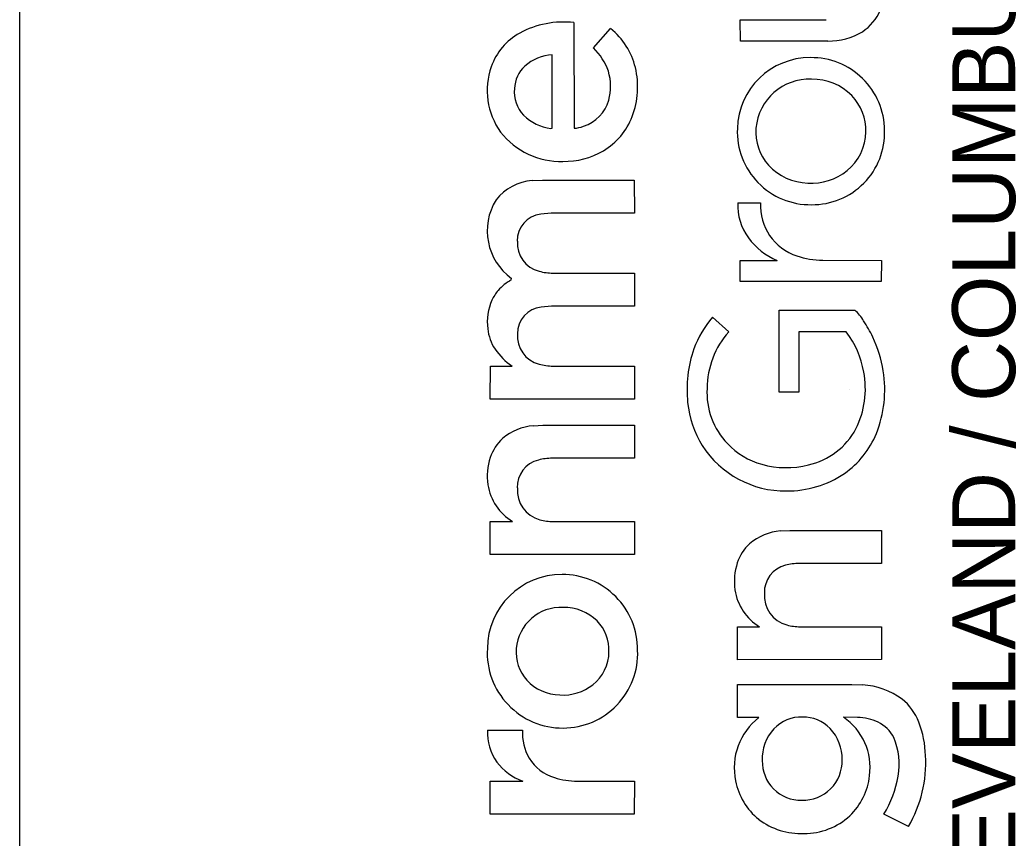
# Model space of a CAD drawing. Extents: x 0 to 34, y 0 to 22.
# Drawn here: x 32 to 32.901, y 3.094 to 3.835 of the extents above; entities that cross this region are included whole.
import ezdxf

# ---------------------------------------------------------------- set-up
doc = ezdxf.new("R2010")
doc.units = 0
doc.layers.add('SH_Border', color=7, linetype='Continuous')
doc.layers.add('SH_Data', color=7, linetype='Continuous')

msp = doc.modelspace()

# ---------------------------------------------------------------- linework, layer by layer
at = {"layer": 'SH_Border'}
msp.add_line((32, 0.5), (32, 21.5), dxfattribs=at)
at = {"layer": 'SH_Data'}
for p, q in [((32.50108, 3.83209), (32.50118, 3.73657)), ((32.65154, 3.83443), (32.72905, 3.8345)), ((32.65165, 3.81543), (32.65154, 3.83443)), ((32.51882, 3.80927), (32.53422, 3.82662)), ((32.73073, 3.81543), (32.65165, 3.81543)), ((32.48144, 3.73644), (32.48144, 3.80296)), ((32.48016, 3.73628), (32.48144, 3.73644)), ((32.46329, 3.68915), (32.47259, 3.68968)), ((32.47259, 3.68968), (32.55557, 3.68968)), ((32.55557, 3.68968), (32.55571, 3.65982)), ((32.64932, 3.66907), (32.66978, 3.66907)), ((32.48058, 3.65981), (32.47102, 3.65881)), ((32.55571, 3.65982), (32.48058, 3.65981)), ((32.65152, 3.61699), (32.68476, 3.617)), ((32.65152, 3.598), (32.65152, 3.61699)), ((32.72605, 3.61703), (32.7791, 3.61696)), ((32.7791, 3.61696), (32.77903, 3.598)), ((32.48218, 3.60553), (32.55571, 3.60548)), ((32.55571, 3.60548), (32.55571, 3.57568)), ((32.44443, 3.59922), (32.44455, 3.60072)), ((32.77903, 3.598), (32.65152, 3.598)), ((32.4809, 3.57567), (32.47143, 3.57474)), ((32.55571, 3.57568), (32.4809, 3.57567)), ((32.6868, 3.57185), (32.75516, 3.57192)), ((32.6868, 3.49778), (32.6868, 3.57185)), ((32.62636, 3.56548), (32.64114, 3.55241)), ((32.70448, 3.55241), (32.70432, 3.49775)), ((32.74737, 3.55227), (32.70448, 3.55241)), ((32.42542, 3.49152), (32.42545, 3.52138)), ((32.42545, 3.52138), (32.44515, 3.52138)), ((32.48206, 3.52138), (32.55571, 3.52136)), ((32.55571, 3.52136), (32.55571, 3.49156)), ((32.70432, 3.49775), (32.6868, 3.49778)), ((32.75, 3.5), (32.75, 3.5)), ((32.55571, 3.49156), (32.42542, 3.49152)), ((32.46439, 3.46736), (32.47289, 3.46783)), ((32.47289, 3.46783), (32.55571, 3.46783)), ((32.55571, 3.46783), (32.55571, 3.43804)), ((32.55571, 3.43804), (32.4814, 3.43796)), ((32.42542, 3.38066), (32.44552, 3.38071)), ((32.42542, 3.35086), (32.42542, 3.38066)), ((32.48222, 3.38071), (32.55569, 3.38071)), ((32.55569, 3.38071), (32.55571, 3.35096)), ((32.68784, 3.3722), (32.69634, 3.37266)), ((32.69634, 3.37266), (32.77916, 3.37266)), ((32.77916, 3.37266), (32.77917, 3.34287)), ((32.55571, 3.35096), (32.42542, 3.35086)), ((32.77917, 3.34287), (32.70485, 3.3428)), ((32.64888, 3.2855), (32.66897, 3.28555)), ((32.64888, 3.25569), (32.64888, 3.2855)), ((32.70568, 3.28555), (32.77915, 3.28555)), ((32.77915, 3.28555), (32.77917, 3.25579)), ((32.77917, 3.25579), (32.64888, 3.25569)), ((32.6489, 3.20336), (32.64889, 3.23322)), ((32.64889, 3.23322), (32.75236, 3.23322)), ((32.75236, 3.23322), (32.76191, 3.23285)), ((32.66836, 3.20336), (32.6489, 3.20336)), ((32.75763, 3.20356), (32.74487, 3.20361)), ((32.42299, 3.19193), (32.45454, 3.19193)), ((32.42542, 3.14577), (32.45473, 3.14579)), ((32.42542, 3.11593), (32.42542, 3.14577)), ((32.50413, 3.14581), (32.55571, 3.14573)), ((32.55571, 3.14573), (32.55565, 3.11593)), ((32.55565, 3.11593), (32.42542, 3.11593)), ((32.8036, 3.10491), (32.7812, 3.11598))]:
    msp.add_line(p, q, dxfattribs=at)
for points in [[(32.50108, 3.83209), (32.50118, 3.73657)], [(32.73073, 3.81543), (32.65165, 3.81543), (32.65154, 3.83443), (32.72905, 3.8345)], [(32.51882, 3.80927), (32.53422, 3.82662)], [(32.48016, 3.73628), (32.48144, 3.73644), (32.48144, 3.80296)], [(32.46329, 3.68915), (32.47259, 3.68968), (32.55557, 3.68968), (32.55571, 3.65982), (32.48058, 3.65981), (32.47102, 3.65881)], [(32.64932, 3.66907), (32.66978, 3.66907)], [(32.72605, 3.61703), (32.7791, 3.61696), (32.77903, 3.598), (32.65152, 3.598)], [(32.65152, 3.598), (32.65152, 3.61699), (32.68476, 3.617)], [(32.48218, 3.60553), (32.55571, 3.60548), (32.55571, 3.57568), (32.4809, 3.57567), (32.47143, 3.57474)], [(32.44443, 3.59922), (32.44455, 3.60072)], [(32.74737, 3.55227), (32.70448, 3.55241), (32.70432, 3.49775), (32.6868, 3.49778), (32.6868, 3.57185), (32.75516, 3.57192)], [(32.62636, 3.56548), (32.64114, 3.55241)], [(32.42542, 3.49152), (32.42545, 3.52138), (32.44515, 3.52138)], [(32.48206, 3.52138), (32.55571, 3.52136), (32.55571, 3.49156), (32.42542, 3.49152)], [(32.46439, 3.46736), (32.47289, 3.46783), (32.55571, 3.46783), (32.55571, 3.43804), (32.4814, 3.43796)], [(32.42542, 3.35086), (32.42542, 3.38066), (32.44552, 3.38071)], [(32.48222, 3.38071), (32.55569, 3.38071), (32.55571, 3.35096), (32.42542, 3.35086)], [(32.68784, 3.3722), (32.69634, 3.37266), (32.77916, 3.37266), (32.77917, 3.34287), (32.70485, 3.3428)], [(32.64888, 3.25569), (32.64888, 3.2855), (32.66897, 3.28555)], [(32.70568, 3.28555), (32.77915, 3.28555), (32.77917, 3.25579), (32.64888, 3.25569)], [(32.66836, 3.20336), (32.6489, 3.20336), (32.64889, 3.23322), (32.75236, 3.23322), (32.76191, 3.23285)], [(32.75763, 3.20356), (32.74487, 3.20361)], [(32.42299, 3.19193), (32.45454, 3.19193)], [(32.50413, 3.14581), (32.55571, 3.14573), (32.55565, 3.11593), (32.42542, 3.11593)], [(32.42542, 3.11593), (32.42542, 3.14577), (32.45473, 3.14579)], [(32.8036, 3.10491), (32.7812, 3.11598)]]:
    msp.add_lwpolyline(points, dxfattribs=at)
for centre, radius, start, end in [((32.739, 3.85901), 0.04201, 303.10391, 338.15613), ((32.739, 3.85901), 0.04201, 303.10391, 338.15613), ((32.49176, 3.74874), 0.08387, 83.62118, 118.28448), ((32.49176, 3.74874), 0.08387, 83.62118, 118.28448), ((32.47894, 3.77368), 0.05583, 118.82935, 160.62242), ((32.47894, 3.77368), 0.05583, 118.82935, 160.62242), ((32.49399, 3.7763), 0.06443, 13.53275, 51.36266), ((32.49399, 3.7763), 0.06443, 13.53275, 51.36266), ((32.7321, 3.87256), 0.05715, 268.62699, 301.47779), ((32.7321, 3.87256), 0.05715, 268.62699, 301.47779), ((32.4844, 3.76071), 0.04236, 94.01311, 130.88062), ((32.4844, 3.76071), 0.04236, 94.01311, 130.88062), ((32.48033, 3.77018), 0.05485, 19.0387, 45.44322), ((32.48033, 3.77018), 0.05485, 19.0387, 45.44322), ((32.71435, 3.73484), 0.06552, 89.48213, 178.77752), ((32.71435, 3.73484), 0.06552, 89.48213, 178.77752), ((32.71582, 3.73414), 0.06623, 0.42265, 90.7613), ((32.71582, 3.73414), 0.06623, 0.42265, 90.7613), ((32.48697, 3.77074), 0.06438, 160.52138, 215.78155), ((32.48697, 3.77074), 0.06438, 160.52138, 215.78155), ((32.47703, 3.7709), 0.02985, 132.98553, 177.1802), ((32.47703, 3.7709), 0.02985, 132.98553, 177.1802), ((32.48724, 3.77433), 0.04701, 344.60723, 17.00675), ((32.48724, 3.77433), 0.04701, 344.60723, 17.00675), ((32.48289, 3.77384), 0.0758, 339.35431, 13.37708), ((32.48289, 3.77384), 0.0758, 339.35431, 13.37708), ((32.71397, 3.73244), 0.04846, 87.68827, 175.01696), ((32.71397, 3.73244), 0.04846, 87.68827, 175.01696), ((32.71659, 3.73036), 0.05052, 44.91202, 90.75914), ((32.71659, 3.73036), 0.05052, 44.91202, 90.75914), ((32.47824, 3.76966), 0.03114, 175.00138, 223.2876), ((32.47824, 3.76966), 0.03114, 175.00138, 223.2876), ((32.71955, 3.73452), 0.04549, 358.32279, 43.83486), ((32.71955, 3.73452), 0.04549, 358.32279, 43.83486), ((32.49895, 3.77177), 0.03504, 288.01084, 343.55364), ((32.49895, 3.77177), 0.03504, 288.01084, 343.55364), ((32.48546, 3.77826), 0.04232, 225.06454, 262.79701), ((32.48546, 3.77826), 0.04232, 225.06454, 262.79701), ((32.49548, 3.76982), 0.0626, 300.94393, 338.73223), ((32.49548, 3.76982), 0.0626, 300.94393, 338.73223), ((32.48908, 3.77516), 0.06872, 217.74341, 271.65606), ((32.48908, 3.77516), 0.06872, 217.74341, 271.65606), ((32.50129, 3.75678), 0.02021, 269.70042, 294.87295), ((32.50129, 3.75678), 0.02021, 269.70042, 294.87295), ((32.71483, 3.7334), 0.06606, 177.53728, 270.94524), ((32.71483, 3.7334), 0.06606, 177.53728, 270.94524), ((32.71085, 3.73311), 0.0453, 175.51467, 221.42047), ((32.71085, 3.73311), 0.0453, 175.51467, 221.42047), ((32.71671, 3.73271), 0.06536, 269.30834, 1.67905), ((32.71671, 3.73271), 0.06536, 269.30834, 1.67905), ((32.71931, 3.73374), 0.04572, 308.90382, 359.30947), ((32.71931, 3.73374), 0.04572, 308.90382, 359.30947), ((32.49204, 3.77702), 0.07055, 269.20529, 300.33566), ((32.49204, 3.77702), 0.07055, 269.20529, 300.33566), ((32.71399, 3.73734), 0.05046, 222.66255, 268.37331), ((32.71399, 3.73734), 0.05046, 222.66255, 268.37331), ((32.71567, 3.73859), 0.05178, 266.55312, 308.67253), ((32.71567, 3.73859), 0.05178, 266.55312, 308.67253), ((32.46638, 3.64404), 0.04521, 93.91118, 142.30723), ((32.46638, 3.64404), 0.04521, 93.91118, 142.30723), ((32.47585, 3.64373), 0.05319, 148.28793, 233.9556), ((32.47585, 3.64373), 0.05319, 148.28793, 233.9556), ((32.69878, 3.66662), 0.04952, 177.16211, 216.28024), ((32.69878, 3.66662), 0.04952, 177.16211, 216.28024), ((32.71735, 3.66638), 0.04764, 176.76988, 252.15044), ((32.71735, 3.66638), 0.04764, 176.76988, 252.15044), ((32.47384, 3.63499), 0.02399, 96.75763, 181.6251), ((32.47384, 3.63499), 0.02399, 96.75763, 181.6251), ((32.47577, 3.63241), 0.02597, 175.81573, 256.16716), ((32.47577, 3.63241), 0.02597, 175.81573, 256.16716), ((32.70975, 3.67555), 0.06366, 216.91526, 246.88619), ((32.70975, 3.67555), 0.06366, 216.91526, 246.88619), ((32.7269, 3.69175), 0.07473, 251.13884, 269.34694), ((32.7269, 3.69175), 0.07473, 251.13884, 269.34694), ((32.4817, 3.65053), 0.04501, 254.34629, 270.61033), ((32.4817, 3.65053), 0.04501, 254.34629, 270.61033), ((32.4638, 3.56267), 0.04137, 117.91625, 139.24296), ((32.4638, 3.56267), 0.04137, 117.91625, 139.24296), ((32.46194, 3.56452), 0.03875, 139.52447, 154.84698), ((32.46194, 3.56452), 0.03875, 139.52447, 154.84698), ((32.47144, 3.5612), 0.04877, 156.06382, 187.3493), ((32.47144, 3.5612), 0.04877, 156.06382, 187.3493), ((32.47421, 3.55056), 0.02434, 96.5532, 179.94902), ((32.47421, 3.55056), 0.02434, 96.5532, 179.94902), ((32.72498, 3.53937), 0.04438, 30.98913, 47.16099), ((32.72498, 3.53937), 0.04438, 30.98913, 47.16099), ((32.70163, 3.50187), 0.09855, 139.79476, 159.13696), ((32.70163, 3.50187), 0.09855, 139.79476, 159.13696), ((32.67091, 3.50018), 0.11106, 25.30315, 33.96179), ((32.67091, 3.50018), 0.11106, 25.30315, 33.96179), ((32.46461, 3.55974), 0.04181, 186.5579, 213.38846), ((32.46461, 3.55974), 0.04181, 186.5579, 213.38846), ((32.47608, 3.54863), 0.02628, 175.722, 255.78627), ((32.47608, 3.54863), 0.02628, 175.722, 255.78627), ((32.69899, 3.50079), 0.07753, 138.25804, 179.70064), ((32.69899, 3.50079), 0.07753, 138.25804, 179.70064), ((32.67889, 3.50099), 0.08556, 10.07509, 36.83189), ((32.67889, 3.50099), 0.08556, 10.07509, 36.83189), ((32.6704, 3.49987), 0.11166, 8.80339, 25.33484), ((32.6704, 3.49987), 0.11166, 8.80339, 25.33484), ((32.47886, 3.57078), 0.0598, 214.70433, 235.68724), ((32.47886, 3.57078), 0.0598, 214.70433, 235.68724), ((32.7187, 3.49968), 0.11536, 161.14379, 185.62812), ((32.7187, 3.49968), 0.11536, 161.14379, 185.62812), ((32.48195, 3.56518), 0.0438, 253.66719, 270.14979), ((32.48195, 3.56518), 0.0438, 253.66719, 270.14979), ((32.68425, 3.50057), 0.08036, 333.46689, 11.03668), ((32.68425, 3.50057), 0.08036, 333.46689, 11.03668), ((32.67564, 3.49977), 0.10649, 338.28866, 9.28548), ((32.67564, 3.49977), 0.10649, 338.28866, 9.28548), ((32.68811, 3.49732), 0.06676, 176.66577, 223.6912), ((32.68811, 3.49732), 0.06676, 176.66577, 223.6912), ((32.69336, 3.49699), 0.08987, 185.50773, 212.01294), ((32.69336, 3.49699), 0.08987, 185.50773, 212.01294), ((32.46871, 3.41767), 0.04988, 94.97056, 130.22484), ((32.46871, 3.41767), 0.04988, 94.97056, 130.22484), ((32.69868, 3.49547), 0.0652, 282.88151, 331.81475), ((32.69868, 3.49547), 0.0652, 282.88151, 331.81475), ((32.69835, 3.49168), 0.08241, 305.03061, 337.67573), ((32.69835, 3.49168), 0.08241, 305.03061, 337.67573), ((32.46348, 3.42602), 0.04016, 132.22383, 161.68229), ((32.46348, 3.42602), 0.04016, 132.22383, 161.68229), ((32.69045, 3.50011), 0.07039, 224.02147, 253.88), ((32.69045, 3.50011), 0.07039, 224.02147, 253.88), ((32.69211, 3.49748), 0.08908, 212.70222, 270.71399), ((32.69211, 3.49748), 0.08908, 212.70222, 270.71399), ((32.47872, 3.42158), 0.05602, 162.27398, 187.79173), ((32.47872, 3.42158), 0.05602, 162.27398, 187.79173), ((32.47482, 3.41206), 0.02498, 103.68683, 182.21395), ((32.47482, 3.41206), 0.02498, 103.68683, 182.21395), ((32.48108, 3.39196), 0.04601, 89.60515, 105.33026), ((32.48108, 3.39196), 0.04601, 89.60515, 105.33026), ((32.69318, 3.51254), 0.08309, 254.45353, 283.9512), ((32.69318, 3.51254), 0.08309, 254.45353, 283.9512), ((32.69429, 3.49979), 0.09138, 269.3273, 304.19632), ((32.69429, 3.49979), 0.09138, 269.3273, 304.19632), ((32.47027, 3.42141), 0.04763, 188.96462, 238.69865), ((32.47027, 3.42141), 0.04763, 188.96462, 238.69865), ((32.47735, 3.40897), 0.02757, 175.58441, 255.13816), ((32.47735, 3.40897), 0.02757, 175.58441, 255.13816), ((32.48183, 3.42286), 0.04215, 254.08913, 270.52838), ((32.48183, 3.42286), 0.04215, 254.08913, 270.52838), ((32.69216, 3.32251), 0.04988, 94.97056, 130.22484), ((32.69216, 3.32251), 0.04988, 94.97056, 130.22484), ((32.68694, 3.33085), 0.04016, 132.22383, 161.68229), ((32.68694, 3.33085), 0.04016, 132.22383, 161.68229), ((32.70217, 3.32642), 0.05602, 162.27398, 187.79173), ((32.70217, 3.32642), 0.05602, 162.27398, 187.79173), ((32.70453, 3.29679), 0.04601, 89.60515, 105.33026), ((32.70453, 3.29679), 0.04601, 89.60515, 105.33026), ((32.69828, 3.31689), 0.02498, 103.68683, 182.21395), ((32.69828, 3.31689), 0.02498, 103.68683, 182.21395), ((32.49014, 3.26543), 0.0674, 89.84756, 179.64047), ((32.49014, 3.26543), 0.0674, 89.84756, 179.64047), ((32.49057, 3.26474), 0.0681, 359.54009, 90.21138), ((32.49057, 3.26474), 0.0681, 359.54009, 90.21138), ((32.69372, 3.32624), 0.04763, 188.96462, 238.69865), ((32.69372, 3.32624), 0.04763, 188.96462, 238.69865), ((32.7008, 3.31381), 0.02757, 175.58441, 255.13816), ((32.7008, 3.31381), 0.02757, 175.58441, 255.13816), ((32.48923, 3.26263), 0.0404, 87.04809, 175.57259), ((32.48923, 3.26263), 0.0404, 87.04809, 175.57259), ((32.49204, 3.25999), 0.04299, 45.84264, 90.98008), ((32.49204, 3.25999), 0.04299, 45.84264, 90.98008), ((32.49458, 3.26421), 0.03821, 357.88569, 44.15902), ((32.49458, 3.26421), 0.03821, 357.88569, 44.15902), ((32.70529, 3.32769), 0.04215, 254.08913, 270.52838), ((32.70529, 3.32769), 0.04215, 254.08913, 270.52838), ((32.49083, 3.26209), 0.06819, 176.8344, 270.40384), ((32.49083, 3.26209), 0.06819, 176.8344, 270.40384), ((32.48729, 3.2625), 0.03848, 175.15378, 221.14706), ((32.48729, 3.2625), 0.03848, 175.15378, 221.14706), ((32.49123, 3.26139), 0.06749, 270.06243, 2.37759), ((32.49123, 3.26139), 0.06749, 270.06243, 2.37759), ((32.49446, 3.26318), 0.0383, 308.28936, 359.43468), ((32.49446, 3.26318), 0.0383, 308.28936, 359.43468), ((32.48919, 3.26607), 0.04228, 223.09994, 268.80895), ((32.48919, 3.26607), 0.04228, 223.09994, 268.80895), ((32.49096, 3.2679), 0.04418, 266.56515, 308.06078), ((32.49096, 3.2679), 0.04418, 266.56515, 308.06078), ((32.75907, 3.16789), 0.06503, 53.40344, 87.49062), ((32.75907, 3.16789), 0.06503, 53.40344, 87.49062), ((32.76517, 3.18039), 0.05141, 21.60748, 50.5577), ((32.76517, 3.18039), 0.05141, 21.60748, 50.5577), ((32.70292, 3.15813), 0.05692, 127.37482, 192.22468), ((32.70292, 3.15813), 0.05692, 127.37482, 192.22468), ((32.70693, 3.16927), 0.0346, 88.47302, 136.42562), ((32.70693, 3.16927), 0.0346, 88.47302, 136.42562), ((32.70814, 3.16963), 0.03424, 44.27195, 90.47623), ((32.70814, 3.16963), 0.03424, 44.27195, 90.47623), ((32.71421, 3.15829), 0.05472, 352.1125, 55.92295), ((32.71421, 3.15829), 0.05472, 352.1125, 55.92295), ((32.75666, 3.15725), 0.04633, 65.01687, 88.8011), ((32.75666, 3.15725), 0.04633, 65.01687, 88.8011), ((32.7626, 3.17155), 0.03085, 26.26808, 63.80301), ((32.7626, 3.17155), 0.03085, 26.26808, 63.80301), ((32.73069, 3.16714), 0.08835, 1.15143, 21.3627), ((32.73069, 3.16714), 0.08835, 1.15143, 21.3627), ((32.46616, 3.18882), 0.04329, 175.87313, 216.34747), ((32.46616, 3.18882), 0.04329, 175.87313, 216.34747), ((32.50087, 3.18948), 0.04639, 176.9688, 209.60636), ((32.50087, 3.18948), 0.04639, 176.9688, 209.60636), ((32.71141, 3.16602), 0.0401, 137.46739, 182.33237), ((32.71141, 3.16602), 0.0401, 137.46739, 182.33237), ((32.70368, 3.166), 0.03996, 358.57141, 43.53765), ((32.70368, 3.166), 0.03996, 358.57141, 43.53765), ((32.73565, 3.16154), 0.05953, 349.30734, 23.43071), ((32.73565, 3.16154), 0.05953, 349.30734, 23.43071), ((32.47466, 3.19716), 0.05511, 218.09809, 248.7907), ((32.47466, 3.19716), 0.05511, 218.09809, 248.7907), ((32.49514, 3.18814), 0.04079, 211.94466, 253.2028), ((32.49514, 3.18814), 0.04079, 211.94466, 253.2028), ((32.70645, 3.1637), 0.03511, 178.88208, 271.08374), ((32.70645, 3.1637), 0.03511, 178.88208, 271.08374), ((32.70818, 3.16404), 0.03546, 268.27882, 1.55016), ((32.70818, 3.16404), 0.03546, 268.27882, 1.55016), ((32.70538, 3.16244), 0.11383, 329.6388, 3.25998), ((32.70538, 3.16244), 0.11383, 329.6388, 3.25998), ((32.50465, 3.2165), 0.07069, 252.46555, 269.57296), ((32.50465, 3.2165), 0.07069, 252.46555, 269.57296), ((32.70463, 3.15696), 0.05837, 190.75182, 231.28919), ((32.70463, 3.15696), 0.05837, 190.75182, 231.28919), ((32.70988, 3.15708), 0.05887, 313.74196, 353.8554), ((32.70988, 3.15708), 0.05887, 313.74196, 353.8554), ((32.70738, 3.16334), 0.08771, 327.31495, 351.57478), ((32.70738, 3.16334), 0.08771, 327.31495, 351.57478), ((32.70632, 3.16112), 0.06269, 232.46061, 272.59022), ((32.70632, 3.16112), 0.06269, 232.46061, 272.59022), ((32.70954, 3.15901), 0.06051, 269.6361, 312.70877), ((32.70954, 3.15901), 0.06051, 269.6361, 312.70877)]:
    msp.add_arc(centre, radius, start, end, dxfattribs=at)

# ---------------------------------------------------------------- texts
msp.add_text('AKRON / CLEVELAND / COLUMBUS', height=0.056969, rotation=90, dxfattribs=at).set_placement((32.90012, 2.638))

doc.saveas('drawing.dxf')
